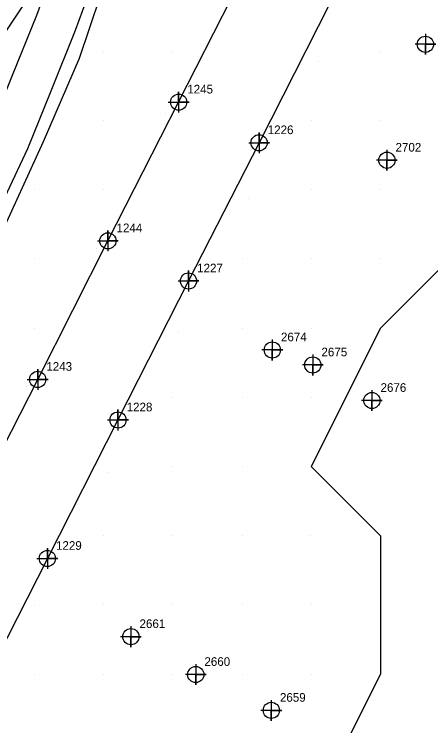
# Model space of a CAD drawing. Extents: x 2062781 to 2066835, y 358981 to 366501.
# Drawn here: x 2064773.1 to 2064893.4, y 362784.8 to 362990.5 of the extents above; entities that cross this region are included whole.
import ezdxf

# ---------------------------------------------------------------- set-up
doc = ezdxf.new("R2010")
doc.units = 0
for name, color, linetype in [('Exist DTM Regular Point CELL', 7, 'Continuous'), ('Exist DTM Regular Point Cogo Number', 7, 'Continuous'), ('Exist Structure Major Deck Tunnel Box Culvert', 7, 'Continuous'), ('Exist Structure Major Deck Tunnel Box Culvert Cogo Number', 7, 'Continuous'), ('Exist Structure Major Deck Tunnel Box Culvert Cogo Point CELL', 7, 'Continuous'), ('PH Exist DTM Breakline', 7, 'Continuous'), ('PH Exist DTM Point', 7, 'Continuous')]:
    doc.layers.add(name, color=color, linetype=linetype)

msp = doc.modelspace()

# ---------------------------------------------------------------- linework, layer by layer
at = {"layer": 'Exist DTM Regular Point CELL'}
for points in [[(2064891.84, 362984.79), (2064891.84, 362978.79), (2064891.84, 362981.79), (2064894.84, 362981.79), (2064888.84, 362981.79)], [(2064880.71, 362951.27), (2064880.71, 362945.27), (2064880.71, 362948.27), (2064883.71, 362948.27), (2064877.71, 362948.27)], [(2064847.61, 362896.45), (2064847.61, 362890.45), (2064847.61, 362893.45), (2064850.61, 362893.45), (2064844.61, 362893.45)], [(2064859.31, 362892.11), (2064859.31, 362886.11), (2064859.31, 362889.11), (2064862.31, 362889.11), (2064856.31, 362889.11)], [(2064876.38, 362881.84), (2064876.38, 362875.84), (2064876.38, 362878.84), (2064879.38, 362878.84), (2064873.38, 362878.84)], [(2064806.76, 362813.59), (2064806.76, 362807.59), (2064806.76, 362810.59), (2064809.76, 362810.59), (2064803.76, 362810.59)], [(2064825.5, 362802.65), (2064825.5, 362796.65), (2064825.5, 362799.65), (2064828.5, 362799.65), (2064822.5, 362799.65)], [(2064847.32, 362792.29), (2064847.32, 362786.29), (2064847.32, 362789.29), (2064850.32, 362789.29), (2064844.32, 362789.29)]]:
    msp.add_lwpolyline(points, dxfattribs=at)
for centre in [(2064891.84, 362981.79), (2064880.71, 362948.27), (2064847.61, 362893.45), (2064859.31, 362889.11), (2064876.38, 362878.84), (2064806.76, 362810.59), (2064825.5, 362799.65), (2064847.32, 362789.29)]:
    msp.add_circle(centre, 2.34, dxfattribs=at)
at = {"layer": 'Exist Structure Major Deck Tunnel Box Culvert'}
for points in [[(2064623.4, 362577.44), (2064650.62, 362630.92), (2064677.82, 362684.31), (2064698.23, 362724.56), (2064718.6, 362764.59), (2064738.99, 362804.71), (2064759.36, 362844.81), (2064779.84, 362884.94), (2064800.12, 362924.98), (2064820.56, 362965.07), (2064840.94, 363005.22), (2064861.36, 363045.25), (2064881.68, 363085.34), (2064902.1, 363125.46), (2064922.64, 363165.68)], [(2064945.77, 363153.79), (2064925.42, 363113.93), (2064904.9, 363073.71), (2064884.54, 363033.52), (2064864.2, 362993.6), (2064843.79, 362953.32), (2064823.4, 362913.38), (2064803.04, 362873.21), (2064782.63, 362833.19), (2064762.2, 362793.01), (2064741.73, 362752.83), (2064721.36, 362712.82), (2064700.92, 362672.65), (2064673.77, 362619.11), (2064646.54, 362565.66)]]:
    msp.add_lwpolyline(points, dxfattribs=at)
at = {"layer": 'Exist Structure Major Deck Tunnel Box Culvert Cogo Point CELL'}
for points in [[(2064817.56, 362965.07), (2064823.56, 362965.07), (2064820.56, 362965.07), (2064820.56, 362968.07), (2064820.56, 362962.07)], [(2064817.56, 362965.07), (2064823.56, 362965.07), (2064820.56, 362965.07), (2064820.56, 362968.07), (2064820.56, 362962.07)], [(2064817.56, 362965.07), (2064823.56, 362965.07), (2064820.56, 362965.07), (2064820.56, 362968.07), (2064820.56, 362962.07)], [(2064840.79, 362953.32), (2064846.79, 362953.32), (2064843.79, 362953.32), (2064843.79, 362956.32), (2064843.79, 362950.32)], [(2064840.79, 362953.32), (2064846.79, 362953.32), (2064843.79, 362953.32), (2064843.79, 362956.32), (2064843.79, 362950.32)], [(2064840.79, 362953.32), (2064846.79, 362953.32), (2064843.79, 362953.32), (2064843.79, 362956.32), (2064843.79, 362950.32)], [(2064797.12, 362924.98), (2064803.12, 362924.98), (2064800.12, 362924.98), (2064800.12, 362927.98), (2064800.12, 362921.98)], [(2064797.12, 362924.98), (2064803.12, 362924.98), (2064800.12, 362924.98), (2064800.12, 362927.98), (2064800.12, 362921.98)], [(2064797.12, 362924.98), (2064803.12, 362924.98), (2064800.12, 362924.98), (2064800.12, 362927.98), (2064800.12, 362921.98)], [(2064820.4, 362913.38), (2064826.4, 362913.38), (2064823.4, 362913.38), (2064823.4, 362916.38), (2064823.4, 362910.38)], [(2064820.4, 362913.38), (2064826.4, 362913.38), (2064823.4, 362913.38), (2064823.4, 362916.38), (2064823.4, 362910.38)], [(2064820.4, 362913.38), (2064826.4, 362913.38), (2064823.4, 362913.38), (2064823.4, 362916.38), (2064823.4, 362910.38)], [(2064776.84, 362884.94), (2064782.84, 362884.94), (2064779.84, 362884.94), (2064779.84, 362887.94), (2064779.84, 362881.94)], [(2064776.84, 362884.94), (2064782.84, 362884.94), (2064779.84, 362884.94), (2064779.84, 362887.94), (2064779.84, 362881.94)], [(2064776.84, 362884.94), (2064782.84, 362884.94), (2064779.84, 362884.94), (2064779.84, 362887.94), (2064779.84, 362881.94)], [(2064800.04, 362873.21), (2064806.04, 362873.21), (2064803.04, 362873.21), (2064803.04, 362876.21), (2064803.04, 362870.21)], [(2064800.04, 362873.21), (2064806.04, 362873.21), (2064803.04, 362873.21), (2064803.04, 362876.21), (2064803.04, 362870.21)], [(2064800.04, 362873.21), (2064806.04, 362873.21), (2064803.04, 362873.21), (2064803.04, 362876.21), (2064803.04, 362870.21)], [(2064779.63, 362833.19), (2064785.63, 362833.19), (2064782.63, 362833.19), (2064782.63, 362836.19), (2064782.63, 362830.19)], [(2064779.63, 362833.19), (2064785.63, 362833.19), (2064782.63, 362833.19), (2064782.63, 362836.19), (2064782.63, 362830.19)], [(2064779.63, 362833.19), (2064785.63, 362833.19), (2064782.63, 362833.19), (2064782.63, 362836.19), (2064782.63, 362830.19)]]:
    msp.add_lwpolyline(points, dxfattribs=at)
for centre in [(2064820.56, 362965.07), (2064820.56, 362965.07), (2064820.56, 362965.07), (2064843.79, 362953.32), (2064843.79, 362953.32), (2064843.79, 362953.32), (2064800.12, 362924.98), (2064800.12, 362924.98), (2064800.12, 362924.98), (2064823.4, 362913.38), (2064823.4, 362913.38), (2064823.4, 362913.38), (2064779.84, 362884.94), (2064779.84, 362884.94), (2064779.84, 362884.94), (2064803.04, 362873.21), (2064803.04, 362873.21), (2064803.04, 362873.21), (2064782.63, 362833.19), (2064782.63, 362833.19), (2064782.63, 362833.19)]:
    msp.add_circle(centre, 2.34, dxfattribs=at)
at = {"layer": 'PH Exist DTM Breakline'}
for points in [[(2064807.3, 363030.11), (2064802.32, 363011.11), (2064797.84, 362995.47), (2064791.78, 362977.67), (2064781.44, 362953.56), (2064768.13, 362924.72), (2064754.4, 362897.09), (2064735.4, 362860.89), (2064708.55, 362807.94), (2064678.24, 362751.31), (2064659.16, 362714.52), (2064643.7, 362686.38), (2064628.13, 362658.09), (2064617.21, 362639.02), (2064609.98, 362625.86), (2064598.02, 362605.33), (2064591.98, 362596.35), (2064587.07, 362588.82), (2064583.37, 362583.25)], [(2064785.71, 363007.19), (2064779.45, 362990.06), (2064772.48, 362972.75), (2064765.86, 362956.39), (2064759.45, 362942.62), (2064749.79, 362923.28), (2064738.37, 362900.81), (2064726.23, 362876.54), (2064713.46, 362852.12), (2064699.51, 362825.61), (2064684.05, 362794.78), (2064670.4, 362769.18), (2064655.54, 362741.04), (2064646.23, 362723.48), (2064637.14, 362706.29), (2064626.33, 362686.94), (2064613.68, 362664.82), (2064602.29, 362645.78), (2064593.55, 362632.4), (2064584.44, 362619.51), (2064571.75, 362603.76), (2064561.33, 362592.06)], [(2064797.04, 363003.22), (2064790.66, 362985.76), (2064783.61, 362968.25), (2064776.87, 362951.61), (2064770.26, 362937.41), (2064760.51, 362917.88), (2064749.09, 362895.41), (2064736.91, 362871.07), (2064724.09, 362846.54), (2064710.18, 362820.13), (2064694.71, 362789.26), (2064681, 362763.56), (2064666.15, 362735.42), (2064656.83, 362717.87), (2064647.69, 362700.56), (2064636.78, 362681.03), (2064624.04, 362658.76), (2064612.46, 362639.42), (2064603.47, 362625.65), (2064594.02, 362612.27), (2064580.91, 362596.01), (2064570.29, 362584.08)], [(2064775.49, 362992.81), (2064770.64, 362985.56)], [(2064938.86, 362939.76), (2064898.86, 362919.76), (2064878.86, 362899.76), (2064858.86, 362859.76), (2064878.86, 362839.76), (2064878.86, 362819.76), (2064878.86, 362799.76), (2064858.86, 362759.76), (2064838.86, 362739.76), (2064818.86, 362719.76), (2064798.86, 362679.76), (2064798.86, 362659.76), (2064778.86, 362639.76), (2064758.86, 362619.76), (2064738.86, 362579.76), (2064738.86, 362559.76), (2064738.86, 362539.76), (2064738.86, 362519.76), (2064738.6, 362499.33), (2064738.86, 362479.76), (2064718.86, 362459.76), (2064698.86, 362459.76), (2064658.86, 362419.76)]]:
    msp.add_lwpolyline(points, dxfattribs=at)
at = {"layer": 'PH Exist DTM Point'}
for p, q in [((2064798.86, 362979.76), (2064798.86, 362979.76)), ((2064818.86, 362979.76), (2064818.86, 362979.76)), ((2064878.86, 362979.76), (2064878.86, 362979.76)), ((2064860.83, 362976.77), (2064860.83, 362976.77)), ((2064816.78, 362961.76), (2064816.78, 362961.76)), ((2064798.86, 362959.76), (2064798.86, 362959.76)), ((2064858.86, 362959.76), (2064858.86, 362959.76)), ((2064878.86, 362959.76), (2064878.86, 362959.76)), ((2064778.86, 362939.76), (2064778.86, 362939.76)), ((2064798.86, 362939.76), (2064798.86, 362939.76)), ((2064858.86, 362939.76), (2064858.86, 362939.76)), ((2064878.86, 362939.76), (2064878.86, 362939.76)), ((2064840.85, 362937.24), (2064840.85, 362937.24)), ((2064796.97, 362922.74), (2064796.97, 362922.74)), ((2064778.86, 362919.76), (2064778.86, 362919.76)), ((2064838.86, 362919.76), (2064838.86, 362919.76)), ((2064858.86, 362919.76), (2064858.86, 362919.76)), ((2064878.86, 362919.76), (2064878.86, 362919.76)), ((2064778.86, 362899.76), (2064778.86, 362899.76)), ((2064838.86, 362899.76), (2064838.86, 362899.76)), ((2064858.86, 362899.76), (2064858.86, 362899.76)), ((2064820.65, 362898.37), (2064820.65, 362898.37)), ((2064776.6, 362882.85), (2064776.6, 362882.85)), ((2064818.86, 362879.76), (2064818.86, 362879.76)), ((2064838.86, 362879.76), (2064838.86, 362879.76)), ((2064858.86, 362879.76), (2064858.86, 362879.76)), ((2064818.86, 362859.76), (2064818.86, 362859.76)), ((2064838.86, 362859.76), (2064838.86, 362859.76)), ((2064800.29, 362858.08), (2064800.29, 362858.08)), ((2064798.86, 362839.76), (2064798.86, 362839.76)), ((2064818.86, 362839.76), (2064818.86, 362839.76)), ((2064838.86, 362839.76), (2064838.86, 362839.76)), ((2064858.77, 362839.84), (2064858.77, 362839.84)), ((2064778.86, 362819.67), (2064778.86, 362819.67)), ((2064798.86, 362819.76), (2064798.86, 362819.76)), ((2064818.86, 362819.76), (2064818.86, 362819.76)), ((2064838.86, 362819.76), (2064838.86, 362819.76)), ((2064858.84, 362819.81), (2064858.84, 362819.81)), ((2064778.86, 362799.76), (2064778.86, 362799.76)), ((2064798.86, 362799.76), (2064798.86, 362799.76)), ((2064818.86, 362799.76), (2064818.86, 362799.76)), ((2064838.86, 362799.76), (2064838.86, 362799.76)), ((2064858.86, 362799.76), (2064858.86, 362799.76))]:
    msp.add_line(p, q, dxfattribs=at)

# ---------------------------------------------------------------- texts
at = {"layer": 'Exist DTM Regular Point Cogo Number'}
for s, p in [('2702', (2064883.21, 362950.77)), ('2702', (2064883.21, 362950.77)), ('2702', (2064883.21, 362950.77)), ('2674', (2064850.11, 362895.95)), ('2674', (2064850.11, 362895.95)), ('2674', (2064850.11, 362895.95)), ('2675', (2064861.81, 362891.61)), ('2675', (2064861.81, 362891.61)), ('2675', (2064861.81, 362891.61)), ('2676', (2064878.88, 362881.34)), ('2676', (2064878.88, 362881.34)), ('2676', (2064878.88, 362881.34)), ('2661', (2064809.26, 362813.09)), ('2661', (2064809.26, 362813.09)), ('2661', (2064809.26, 362813.09)), ('2660', (2064828, 362802.15)), ('2660', (2064828, 362802.15)), ('2660', (2064828, 362802.15)), ('2659', (2064849.82, 362791.79)), ('2659', (2064849.82, 362791.79)), ('2659', (2064849.82, 362791.79))]:
    msp.add_text(s, height=2.5, dxfattribs=at).set_placement(p)
at = {"layer": 'Exist Structure Major Deck Tunnel Box Culvert Cogo Number'}
for s, p in [('1245', (2064823.06, 362967.57)), ('1245', (2064823.06, 362967.57)), ('1245', (2064823.06, 362967.57)), ('1226', (2064846.29, 362955.82)), ('1226', (2064846.29, 362955.82)), ('1226', (2064846.29, 362955.82)), ('1244', (2064802.62, 362927.48)), ('1244', (2064802.62, 362927.48)), ('1244', (2064802.62, 362927.48)), ('1227', (2064825.9, 362915.88)), ('1227', (2064825.9, 362915.88)), ('1227', (2064825.9, 362915.88)), ('1243', (2064782.34, 362887.44)), ('1243', (2064782.34, 362887.44)), ('1243', (2064782.34, 362887.44)), ('1228', (2064805.54, 362875.71)), ('1228', (2064805.54, 362875.71)), ('1228', (2064805.54, 362875.71)), ('1229', (2064785.13, 362835.69)), ('1229', (2064785.13, 362835.69)), ('1229', (2064785.13, 362835.69))]:
    msp.add_text(s, height=2.5, dxfattribs=at).set_placement(p)

doc.saveas('drawing.dxf')
